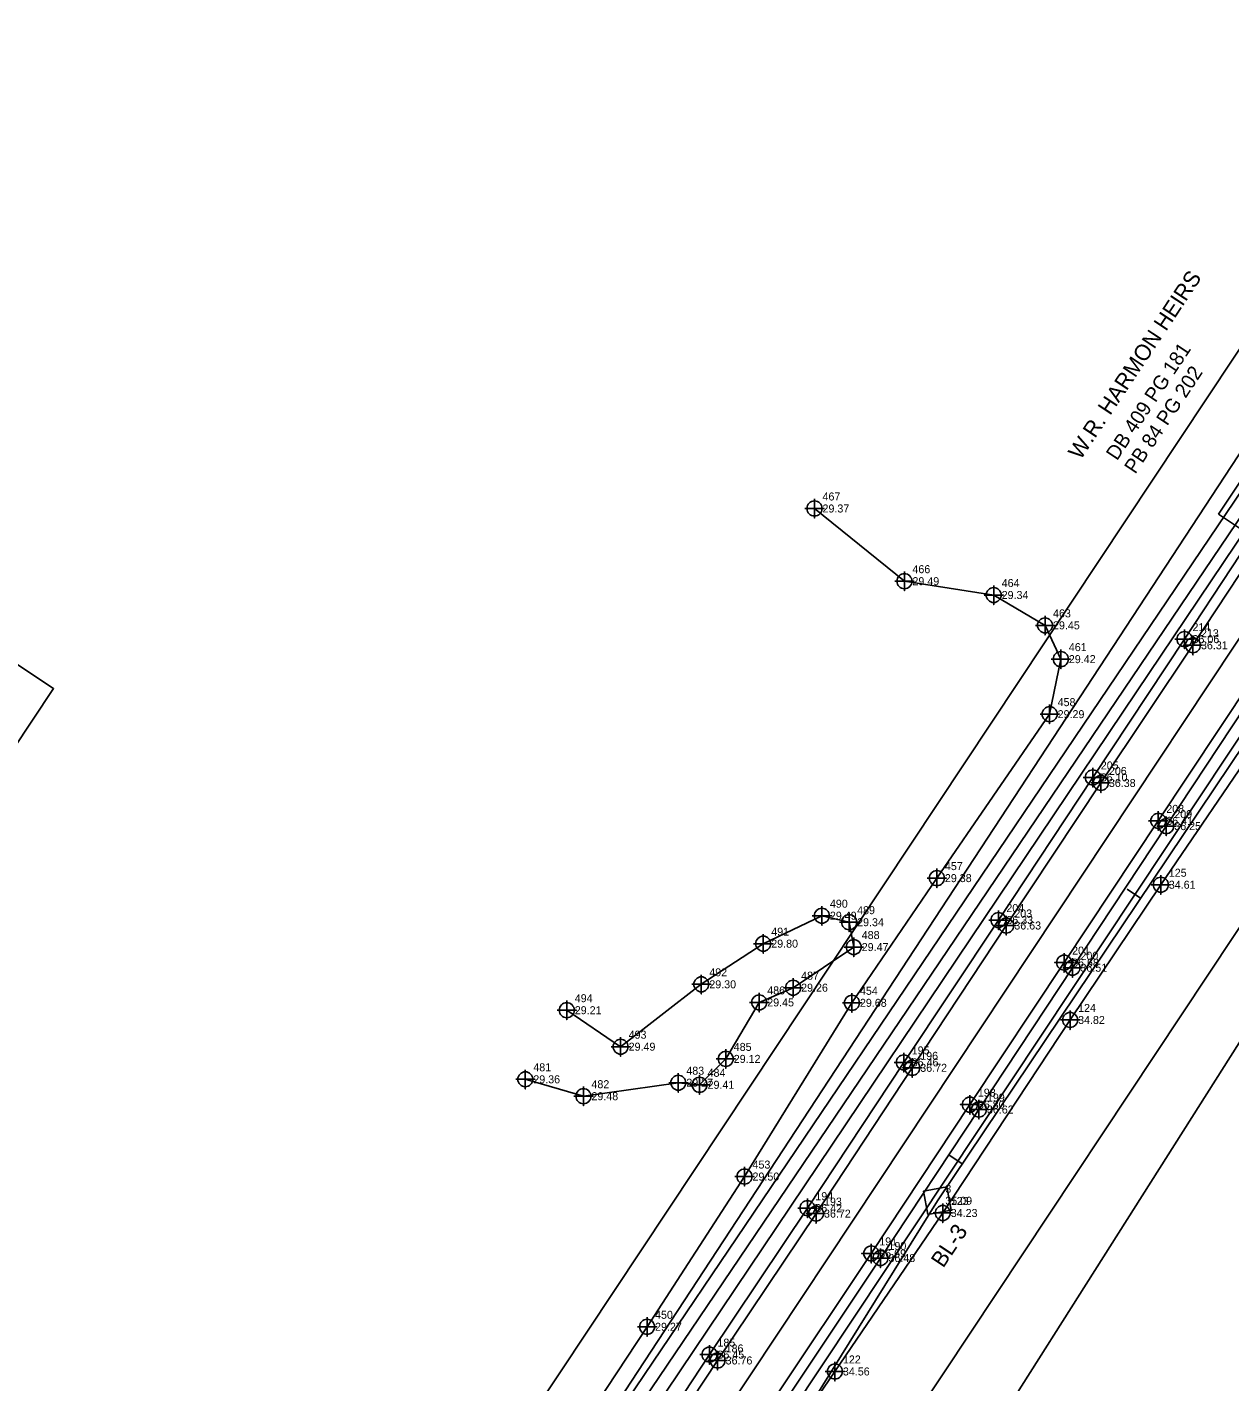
# Model space of a CAD drawing. Extents: x 2603627 to 2605187, y 896619 to 899063.
# Drawn here: x 2604017.2 to 2604393.2, y 897705.9 to 898129.3 of the extents above; entities that cross this region are included whole.
import ezdxf

# ---------------------------------------------------------------- set-up
doc = ezdxf.new("R2010")
doc.units = 0
for name, color, linetype in [('CTL Sheet Datum Description CELL', 7, 'Continuous'), ('CTL Supplemental Horizontal and Vertical CELL', 7, 'Continuous'), ('CTL Supplemental Horizontal and Vertical Cogo Elevation', 7, 'Continuous'), ('CTL Supplemental Horizontal and Vertical Cogo Number', 7, 'Continuous'), ('CTL Supplemental Horizontal and Vertical Text', 7, 'Continuous'), ('Exist Horizontal Alignment', 7, 'Continuous'), ('Exist Horizontal Baseline Alignment', 7, 'Continuous'), ('Exist Horizontal Baseline Alignment Tick small', 7, 'Continuous'), ('Exist Hydro Stream or Body of Water', 7, 'Continuous'), ('Exist Hydro Stream or Body of Water Cogo Elevation', 7, 'Continuous'), ('Exist Hydro Stream or Body of Water Cogo Number', 7, 'Continuous'), ('Exist Hydro Stream or Body of Water Cogo Point CELL', 7, 'Continuous'), ('Exist Property Deed Book Text', 7, 'Continuous'), ('Exist Property Owner Text', 7, 'Continuous'), ('Exist Right of Way Line', 7, 'Continuous'), ('Exist Roads EOP', 7, 'Continuous'), ('Exist Roads EOP Cogo Elevation', 7, 'Continuous'), ('Exist Roads EOP Cogo Number', 7, 'Continuous'), ('Exist Roads EOP Cogo Point CELL', 7, 'Continuous'), ('Exist Roads EOT', 7, 'Continuous'), ('Exist Roads EOT Cogo Elevation', 7, 'Continuous'), ('Exist Roads EOT Cogo Number', 7, 'Continuous'), ('Exist Roads EOT Cogo Point CELL', 7, 'Continuous'), ('Exist Utilities Telephone UG Cable SUE LOS C', 7, 'Continuous'), ('Exist Utilities Telephone UG FO SUE LOS C', 7, 'Continuous'), ('Exist Utilities Water UG Line SUE LOS B', 7, 'Continuous'), ('Exist Utilities Water UG Line SUE LOS B Cogo Elevation', 7, 'Continuous'), ('Exist Utilities Water UG Line SUE LOS B Cogo Number', 7, 'Continuous'), ('Exist Utilities Water UG Line SUE LOS B Cogo Point CELL', 7, 'Continuous'), ('Exist Vegetation Woods Line', 7, 'Continuous')]:
    doc.layers.add(name, color=color, linetype=linetype)

# ---------------------------------------------------------------- blocks, each defined once
blk = doc.blocks.new('EXIST UTILITIES WATER UG LINE SUE LOS B COGO POINT')
at = {"layer": 'Exist Utilities Water UG Line SUE LOS B Cogo Point CELL'}
blk.add_lwpolyline([(0, 0.06), (0, -0.06), (0, 0), (0.06, 0), (-0.06, 0)], dxfattribs=at)
blk.add_circle((0, 0), 0.0469, dxfattribs=at)
blk = doc.blocks.new('EXIST ROADS EOP COGO POINT')
at = {"layer": 'Exist Roads EOP Cogo Point CELL'}
blk.add_lwpolyline([(0, 0.06), (0, -0.06), (0, 0), (0.06, 0), (-0.06, 0)], dxfattribs=at)
blk.add_circle((0, 0), 0.0469, dxfattribs=at)
blk = doc.blocks.new('EXIST ROADS EOT COGO POINT')
at = {"layer": 'Exist Roads EOT Cogo Point CELL'}
blk.add_lwpolyline([(0, 0.06), (0, -0.06), (0, 0), (-0.06, 0), (0.06, 0)], dxfattribs=at)
blk.add_circle((0, 0), 0.0469, dxfattribs=at)
blk = doc.blocks.new('EXIST HYDRO STREAM OR BODY OF WATER COGO POINT')
at = {"layer": 'Exist Hydro Stream or Body of Water Cogo Point CELL'}
blk.add_lwpolyline([(-0.06, 0), (0.06, 0), (0, 0), (0, -0.06), (0, 0.06)], dxfattribs=at)
blk.add_circle((0, 0), 0.0469, dxfattribs=at)
blk = doc.blocks.new('CTL SUPPLEMENTAL HORIZONTAL AND VERTICAL')
at = {"layer": 'CTL Supplemental Horizontal and Vertical CELL'}
blk.add_line((0, 0), (0, 0), dxfattribs=at)
blk.add_lwpolyline([(-0.1043, 0.0004), (0.0005, 0.1052), (0.1055, 0.0002), (0.0007, -0.1047)], close=True, dxfattribs=at)

msp = doc.modelspace()

# ---------------------------------------------------------------- linework, layer by layer
at = {"layer": 'CTL Sheet Datum Description CELL'}
msp.add_lwpolyline([(2603889.35, 897717.65), (2603748.58, 897811.15), (2603884.68, 898016.07), (2604025.46, 897922.57)], close=True, dxfattribs=at)
at = {"layer": 'Exist Horizontal Alignment'}
msp.add_line((2604046.33, 897411.6), (2604501.12, 898096.36), dxfattribs=at)
at = {"layer": 'Exist Horizontal Baseline Alignment'}
for p, q in [((2604301.74, 897762.53), (2604544.96, 898124.44)), ((2604070.2, 897390.44), (2604301.74, 897762.53))]:
    msp.add_line(p, q, dxfattribs=at)
at = {"layer": 'Exist Horizontal Baseline Alignment Tick small'}
for p, q in [((2604365.28, 897857.07), (2604361.13, 897859.86)), ((2604309.5, 897774.07), (2604305.35, 897776.86))]:
    msp.add_line(p, q, dxfattribs=at)
at = {"layer": 'Exist Hydro Stream or Body of Water'}
for points in [[(2604052.91, 897628.09), (2604089.6, 897627.32), (2604128.24, 897636.3), (2604156.3, 897646.97), (2604185.61, 897684.58), (2604210.99, 897723.15), (2604241.46, 897770.09), (2604275.04, 897824.38), (2604301.6, 897863.35), (2604336.85, 897914.58), (2604340.35, 897931.78), (2604335.4, 897942.33), (2604319.35, 897951.81), (2604291.45, 897956.13), (2604263.34, 897978.85)], [(2604172.93, 897800.48), (2604191.1, 897795.2), (2604220.76, 897799.42), (2604227.41, 897798.77), (2604235.59, 897806.86), (2604246.06, 897824.51), (2604256.65, 897829.11), (2604275.6, 897841.8), (2604274.16, 897849.57), (2604265.65, 897851.6), (2604247.31, 897842.86), (2604227.95, 897830.16), (2604202.73, 897810.66), (2604185.89, 897822.07)]]:
    msp.add_lwpolyline(points, dxfattribs=at)
at = {"layer": 'Exist Right of Way Line'}
for p, q in [((2604004.68, 897439.26), (2604459.47, 898124.02)), ((2604087.98, 897383.94), (2604542.77, 898068.69))]:
    msp.add_line(p, q, dxfattribs=at)
at = {"layer": 'Exist Roads EOP'}
for points in [[(2604034.94, 897419.16), (2604054.97, 897449.51), (2604085.58, 897495.18), (2604114.88, 897539.87), (2604143.93, 897583.57), (2604172.72, 897627.19), (2604201.64, 897670.62), (2604230.5, 897714.45), (2604261.1, 897760.21), (2604291.23, 897805.76), (2604320.82, 897850.24), (2604350.34, 897894.81), (2604379.01, 897938.02), (2604408.4, 897982.56), (2604438.29, 898027.28), (2604468.22, 898072.28), (2604496.92, 898115.7)], [(2604057.72, 897404.05), (2604078.22, 897434.83), (2604108.36, 897480.05), (2604137.93, 897524.86), (2604167.35, 897568.96), (2604196.06, 897612.17), (2604224.86, 897655.68), (2604253.51, 897698.95), (2604283.96, 897744.64), (2604314.74, 897791.03), (2604343.97, 897835.34), (2604373.31, 897879.6), (2604402.1, 897923.18), (2604431.64, 897967.59), (2604461.24, 898012.02), (2604491.05, 898056.88), (2604519.7, 898100.47)]]:
    msp.add_lwpolyline(points, dxfattribs=at)
at = {"layer": 'Exist Roads EOT'}
for points in [[(2604037.37, 897417.54), (2604057.46, 897447.93), (2604087.91, 897493.66), (2604117.35, 897538.28), (2604146.54, 897581.98), (2604175.28, 897625.51), (2604204.1, 897668.97), (2604233.05, 897712.63), (2604263.81, 897758.51), (2604293.89, 897804.07), (2604323.3, 897848.54), (2604352.86, 897893.08), (2604381.65, 897936.11), (2604411.04, 897980.65), (2604440.78, 898025.82), (2604470.61, 898070.74), (2604499.36, 898114.11)], [(2604055.13, 897405.77), (2604075.39, 897436.3), (2604105.72, 897481.84), (2604135.41, 897526.58), (2604164.51, 897570.47), (2604193.14, 897613.84), (2604222.02, 897657.58), (2604250.73, 897700.63), (2604281.08, 897746.07), (2604311.9, 897792.56), (2604341.37, 897836.94), (2604370.82, 897881.24), (2604399.64, 897924.71), (2604429.03, 897968.88), (2604458.85, 898013.95), (2604488.44, 898058.33), (2604517.14, 898101.52)]]:
    msp.add_lwpolyline(points, dxfattribs=at)
at = {"layer": 'Exist Utilities Telephone UG Cable SUE LOS C'}
for p, q in [((2604364.02, 897921.59), (2604492.57, 898112.76)), ((2604389.62, 897977.06), (2604474.1, 898104.18)), ((2604426.24, 897952.72), (2604389.62, 897977.06)), ((2604201.56, 897614.6), (2604426.24, 897952.72)), ((2604109.59, 897543.22), (2604364.02, 897921.59))]:
    msp.add_line(p, q, dxfattribs=at)
at = {"layer": 'Exist Utilities Telephone UG FO SUE LOS C'}
for p, q in [((2604020.98, 897428.41), (2604461.82, 898080.46)), ((2604024.53, 897426.06), (2604465.37, 898078.1))]:
    msp.add_line(p, q, dxfattribs=at)
at = {"layer": 'Exist Utilities Water UG Line SUE LOS B'}
msp.add_lwpolyline([(2604076.5, 897391.6), (2604089.19, 897412.44), (2604108.02, 897444.81), (2604130.46, 897486.17), (2604138.61, 897502.5), (2604141.74, 897510.42), (2604157.29, 897542.11), (2604195.61, 897598.86), (2604232.99, 897655.2), (2604269.72, 897709.19), (2604303.43, 897758.71), (2604343.24, 897819.02), (2604371.6, 897861.28), (2604402.52, 897906.63), (2604434.42, 897955.25), (2604460.63, 897996.69), (2604477.79, 898022.59), (2604502.25, 898059.64), (2604529.4, 898098.89), (2604530.47, 898100.43), (2604537.02, 898109.88), (2604550.55, 898129.28)], dxfattribs=at)
at = {"layer": 'Exist Vegetation Woods Line'}
for points in [[(2604476.15, 898117.83), (2604185.5, 897674.67)], [(2604278.2, 897626.01), (2604559.06, 898068.86)]]:
    msp.add_lwpolyline(points, dxfattribs=at)

# ---------------------------------------------------------------- block references
at = {"layer": 'CTL Supplemental Horizontal and Vertical CELL', "xscale": 50, "yscale": 50, "rotation": 55.88070136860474}
msp.add_blockref('CTL SUPPLEMENTAL HORIZONTAL AND VERTICAL', (2604301.74, 897762.53), dxfattribs=at)
at = {"layer": 'Exist Hydro Stream or Body of Water Cogo Point CELL', "xscale": 50, "yscale": 50}
for p in [(2604263.34, 897978.85), (2604291.45, 897956.13), (2604319.35, 897951.81), (2604335.4, 897942.33), (2604340.35, 897931.78), (2604336.85, 897914.58), (2604301.6, 897863.35), (2604265.65, 897851.6), (2604274.16, 897849.57), (2604247.31, 897842.86), (2604275.6, 897841.8), (2604227.95, 897830.16), (2604256.65, 897829.11), (2604246.06, 897824.51), (2604275.04, 897824.38), (2604185.89, 897822.07), (2604202.73, 897810.66), (2604235.59, 897806.86), (2604172.93, 897800.48), (2604220.76, 897799.42), (2604191.1, 897795.2), (2604227.41, 897798.77), (2604241.46, 897770.09), (2604210.99, 897723.15)]:
    msp.add_blockref('EXIST HYDRO STREAM OR BODY OF WATER COGO POINT', p, dxfattribs=at)
at = {"layer": 'Exist Roads EOP Cogo Point CELL', "xscale": 50, "yscale": 50}
for p in [(2604379.01, 897938.02), (2604350.34, 897894.81), (2604373.31, 897879.6), (2604320.82, 897850.24), (2604343.97, 897835.34), (2604291.23, 897805.76), (2604314.74, 897791.03), (2604261.1, 897760.21), (2604283.96, 897744.64), (2604230.5, 897714.45)]:
    msp.add_blockref('EXIST ROADS EOP COGO POINT', p, dxfattribs=at)
at = {"layer": 'Exist Roads EOT Cogo Point CELL', "xscale": 50, "yscale": 50}
for p in [(2604381.65, 897936.11), (2604352.86, 897893.08), (2604370.82, 897881.24), (2604323.3, 897848.54), (2604341.37, 897836.94), (2604293.89, 897804.07), (2604311.9, 897792.56), (2604263.81, 897758.51), (2604281.08, 897746.07), (2604233.05, 897712.63)]:
    msp.add_blockref('EXIST ROADS EOT COGO POINT', p, dxfattribs=at)
at = {"layer": 'Exist Utilities Water UG Line SUE LOS B Cogo Point CELL', "xscale": 50, "yscale": 50}
for p in [(2604371.6, 897861.28), (2604343.24, 897819.02), (2604303.43, 897758.71), (2604269.72, 897709.19)]:
    msp.add_blockref('EXIST UTILITIES WATER UG LINE SUE LOS B COGO POINT', p, dxfattribs=at)

# ---------------------------------------------------------------- texts
at = {"layer": 'CTL Supplemental Horizontal and Vertical Cogo Elevation'}
msp.add_text('35.09', height=2.5, dxfattribs=at).set_placement((2604304.24, 897761.28))
at = {"layer": 'CTL Supplemental Horizontal and Vertical Cogo Number'}
msp.add_text('3', height=2.5, dxfattribs=at).set_placement((2604304.24, 897765.03))
at = {"layer": 'CTL Supplemental Horizontal and Vertical Text'}
msp.add_text('BL-3', height=5, rotation=56.4094, dxfattribs=at).set_placement((2604303.58, 897741.29))
at = {"layer": 'Exist Hydro Stream or Body of Water Cogo Elevation'}
for s, p in [('29.37', (2604265.84, 897977.6)), ('29.49', (2604293.95, 897954.88)), ('29.34', (2604321.85, 897950.56)), ('29.45', (2604337.9, 897941.08)), ('29.42', (2604342.85, 897930.53)), ('29.29', (2604339.35, 897913.33)), ('29.38', (2604304.1, 897862.1)), ('29.49', (2604268.15, 897850.35)), ('29.34', (2604276.66, 897848.32)), ('29.80', (2604249.81, 897841.61)), ('29.47', (2604278.1, 897840.55)), ('29.30', (2604230.45, 897828.91)), ('29.26', (2604259.15, 897827.86)), ('29.21', (2604188.39, 897820.82)), ('29.45', (2604248.56, 897823.26)), ('29.68', (2604277.54, 897823.13)), ('29.49', (2604205.23, 897809.42)), ('29.12', (2604238.09, 897805.61)), ('29.36', (2604175.43, 897799.23)), ('29.27', (2604223.26, 897798.17)), ('29.41', (2604229.91, 897797.52)), ('29.48', (2604193.6, 897793.95)), ('29.50', (2604243.96, 897768.84)), ('29.27', (2604213.49, 897721.9))]:
    msp.add_text(s, height=2.5, dxfattribs=at).set_placement(p)
at = {"layer": 'Exist Hydro Stream or Body of Water Cogo Number'}
for s, p in [('467', (2604265.84, 897981.35)), ('466', (2604293.95, 897958.63)), ('464', (2604321.85, 897954.31)), ('463', (2604337.9, 897944.83)), ('461', (2604342.85, 897934.28)), ('458', (2604339.35, 897917.08)), ('457', (2604304.1, 897865.85)), ('490', (2604268.15, 897854.1)), ('489', (2604276.66, 897852.07)), ('491', (2604249.81, 897845.36)), ('488', (2604278.1, 897844.3)), ('492', (2604230.45, 897832.66)), ('487', (2604259.15, 897831.61)), ('486', (2604248.56, 897827.01)), ('454', (2604277.54, 897826.88)), ('494', (2604188.39, 897824.57)), ('493', (2604205.23, 897813.17)), ('485', (2604238.09, 897809.36)), ('481', (2604175.43, 897802.98)), ('483', (2604223.26, 897801.92)), ('484', (2604229.91, 897801.27)), ('482', (2604193.6, 897797.7)), ('453', (2604243.96, 897772.59)), ('450', (2604213.49, 897725.65))]:
    msp.add_text(s, height=2.5, dxfattribs=at).set_placement(p)
at = {"layer": 'Exist Property Deed Book Text'}
for s, p in [('DB 409 PG 181', (2604357.9, 897993.59)), ('PB 84 PG 202', (2604363.61, 897989.4))]:
    msp.add_text(s, height=4.5, rotation=56.4133, dxfattribs=at).set_placement(p)
at = {"layer": 'Exist Property Owner Text'}
msp.add_text('W.R. HARMON HEIRS', height=5, rotation=56.4133, dxfattribs=at).set_placement((2604346.51, 897993.77))
at = {"layer": 'Exist Roads EOP Cogo Elevation'}
for s, p in [('36.06', (2604381.51, 897936.77)), ('36.10', (2604352.84, 897893.56)), ('36.25', (2604375.81, 897878.35)), ('36.33', (2604323.32, 897848.99)), ('36.51', (2604346.47, 897834.09)), ('36.46', (2604293.73, 897804.51)), ('36.62', (2604317.24, 897789.78)), ('36.42', (2604263.6, 897758.96)), ('36.48', (2604286.46, 897743.39)), ('36.45', (2604233, 897713.2))]:
    msp.add_text(s, height=2.5, dxfattribs=at).set_placement(p)
at = {"layer": 'Exist Roads EOP Cogo Number'}
for s, p in [('214', (2604381.51, 897940.52)), ('205', (2604352.84, 897897.31)), ('209', (2604375.81, 897882.1)), ('204', (2604323.32, 897852.74)), ('200', (2604346.47, 897837.84)), ('195', (2604293.73, 897808.26)), ('199', (2604317.24, 897793.53)), ('194', (2604263.6, 897762.71)), ('190', (2604286.46, 897747.14)), ('185', (2604233, 897716.95))]:
    msp.add_text(s, height=2.5, dxfattribs=at).set_placement(p)
at = {"layer": 'Exist Roads EOT Cogo Elevation'}
for s, p in [('36.31', (2604384.15, 897934.86)), ('36.38', (2604355.36, 897891.83)), ('36.41', (2604373.32, 897879.99)), ('36.63', (2604325.8, 897847.29)), ('36.68', (2604343.87, 897835.69)), ('36.72', (2604296.39, 897802.82)), ('36.80', (2604314.4, 897791.31)), ('36.72', (2604266.31, 897757.26)), ('36.69', (2604283.58, 897744.82)), ('36.76', (2604235.55, 897711.38))]:
    msp.add_text(s, height=2.5, dxfattribs=at).set_placement(p)
at = {"layer": 'Exist Roads EOT Cogo Number'}
for s, p in [('213', (2604384.15, 897938.61)), ('206', (2604355.36, 897895.58)), ('208', (2604373.32, 897883.74)), ('203', (2604325.8, 897851.04)), ('201', (2604343.87, 897839.44)), ('196', (2604296.39, 897806.57)), ('198', (2604314.4, 897795.06)), ('193', (2604266.31, 897761.01)), ('191', (2604283.58, 897748.57)), ('186', (2604235.55, 897715.13))]:
    msp.add_text(s, height=2.5, dxfattribs=at).set_placement(p)
at = {"layer": 'Exist Utilities Water UG Line SUE LOS B Cogo Elevation'}
for s, p in [('34.61', (2604374.1, 897860.03)), ('34.82', (2604345.74, 897817.77)), ('34.23', (2604305.93, 897757.46)), ('34.56', (2604272.22, 897707.94))]:
    msp.add_text(s, height=2.5, dxfattribs=at).set_placement(p)
at = {"layer": 'Exist Utilities Water UG Line SUE LOS B Cogo Number'}
for s, p in [('125', (2604374.1, 897863.78)), ('124', (2604345.74, 897821.52)), ('123', (2604305.93, 897761.21)), ('122', (2604272.22, 897711.69))]:
    msp.add_text(s, height=2.5, dxfattribs=at).set_placement(p)

doc.saveas('drawing.dxf')
